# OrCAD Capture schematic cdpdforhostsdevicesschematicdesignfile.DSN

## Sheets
1 2 History_Sheet: title: CD_PD_Hosts_Devices; rev: 1.5
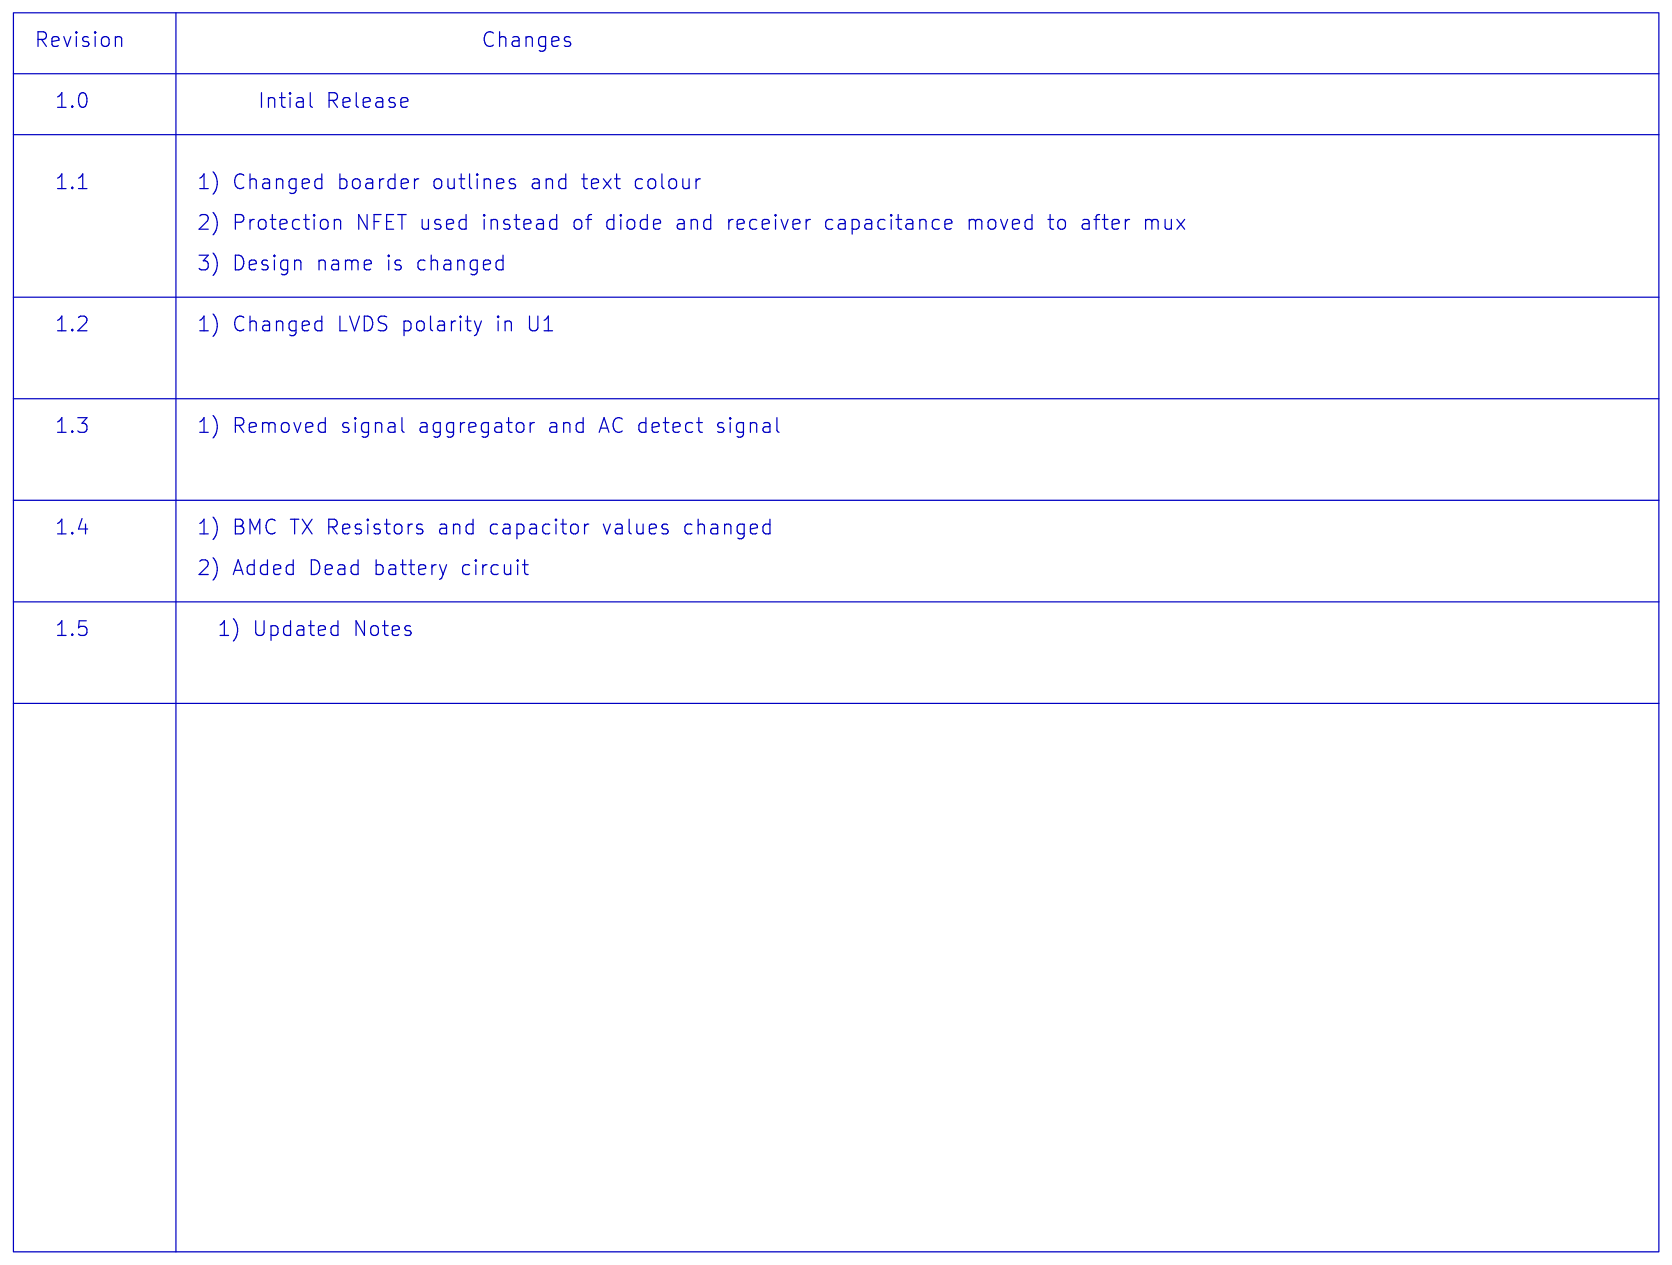
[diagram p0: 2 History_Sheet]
2 1 CD_PD_Host_ Devices: size B
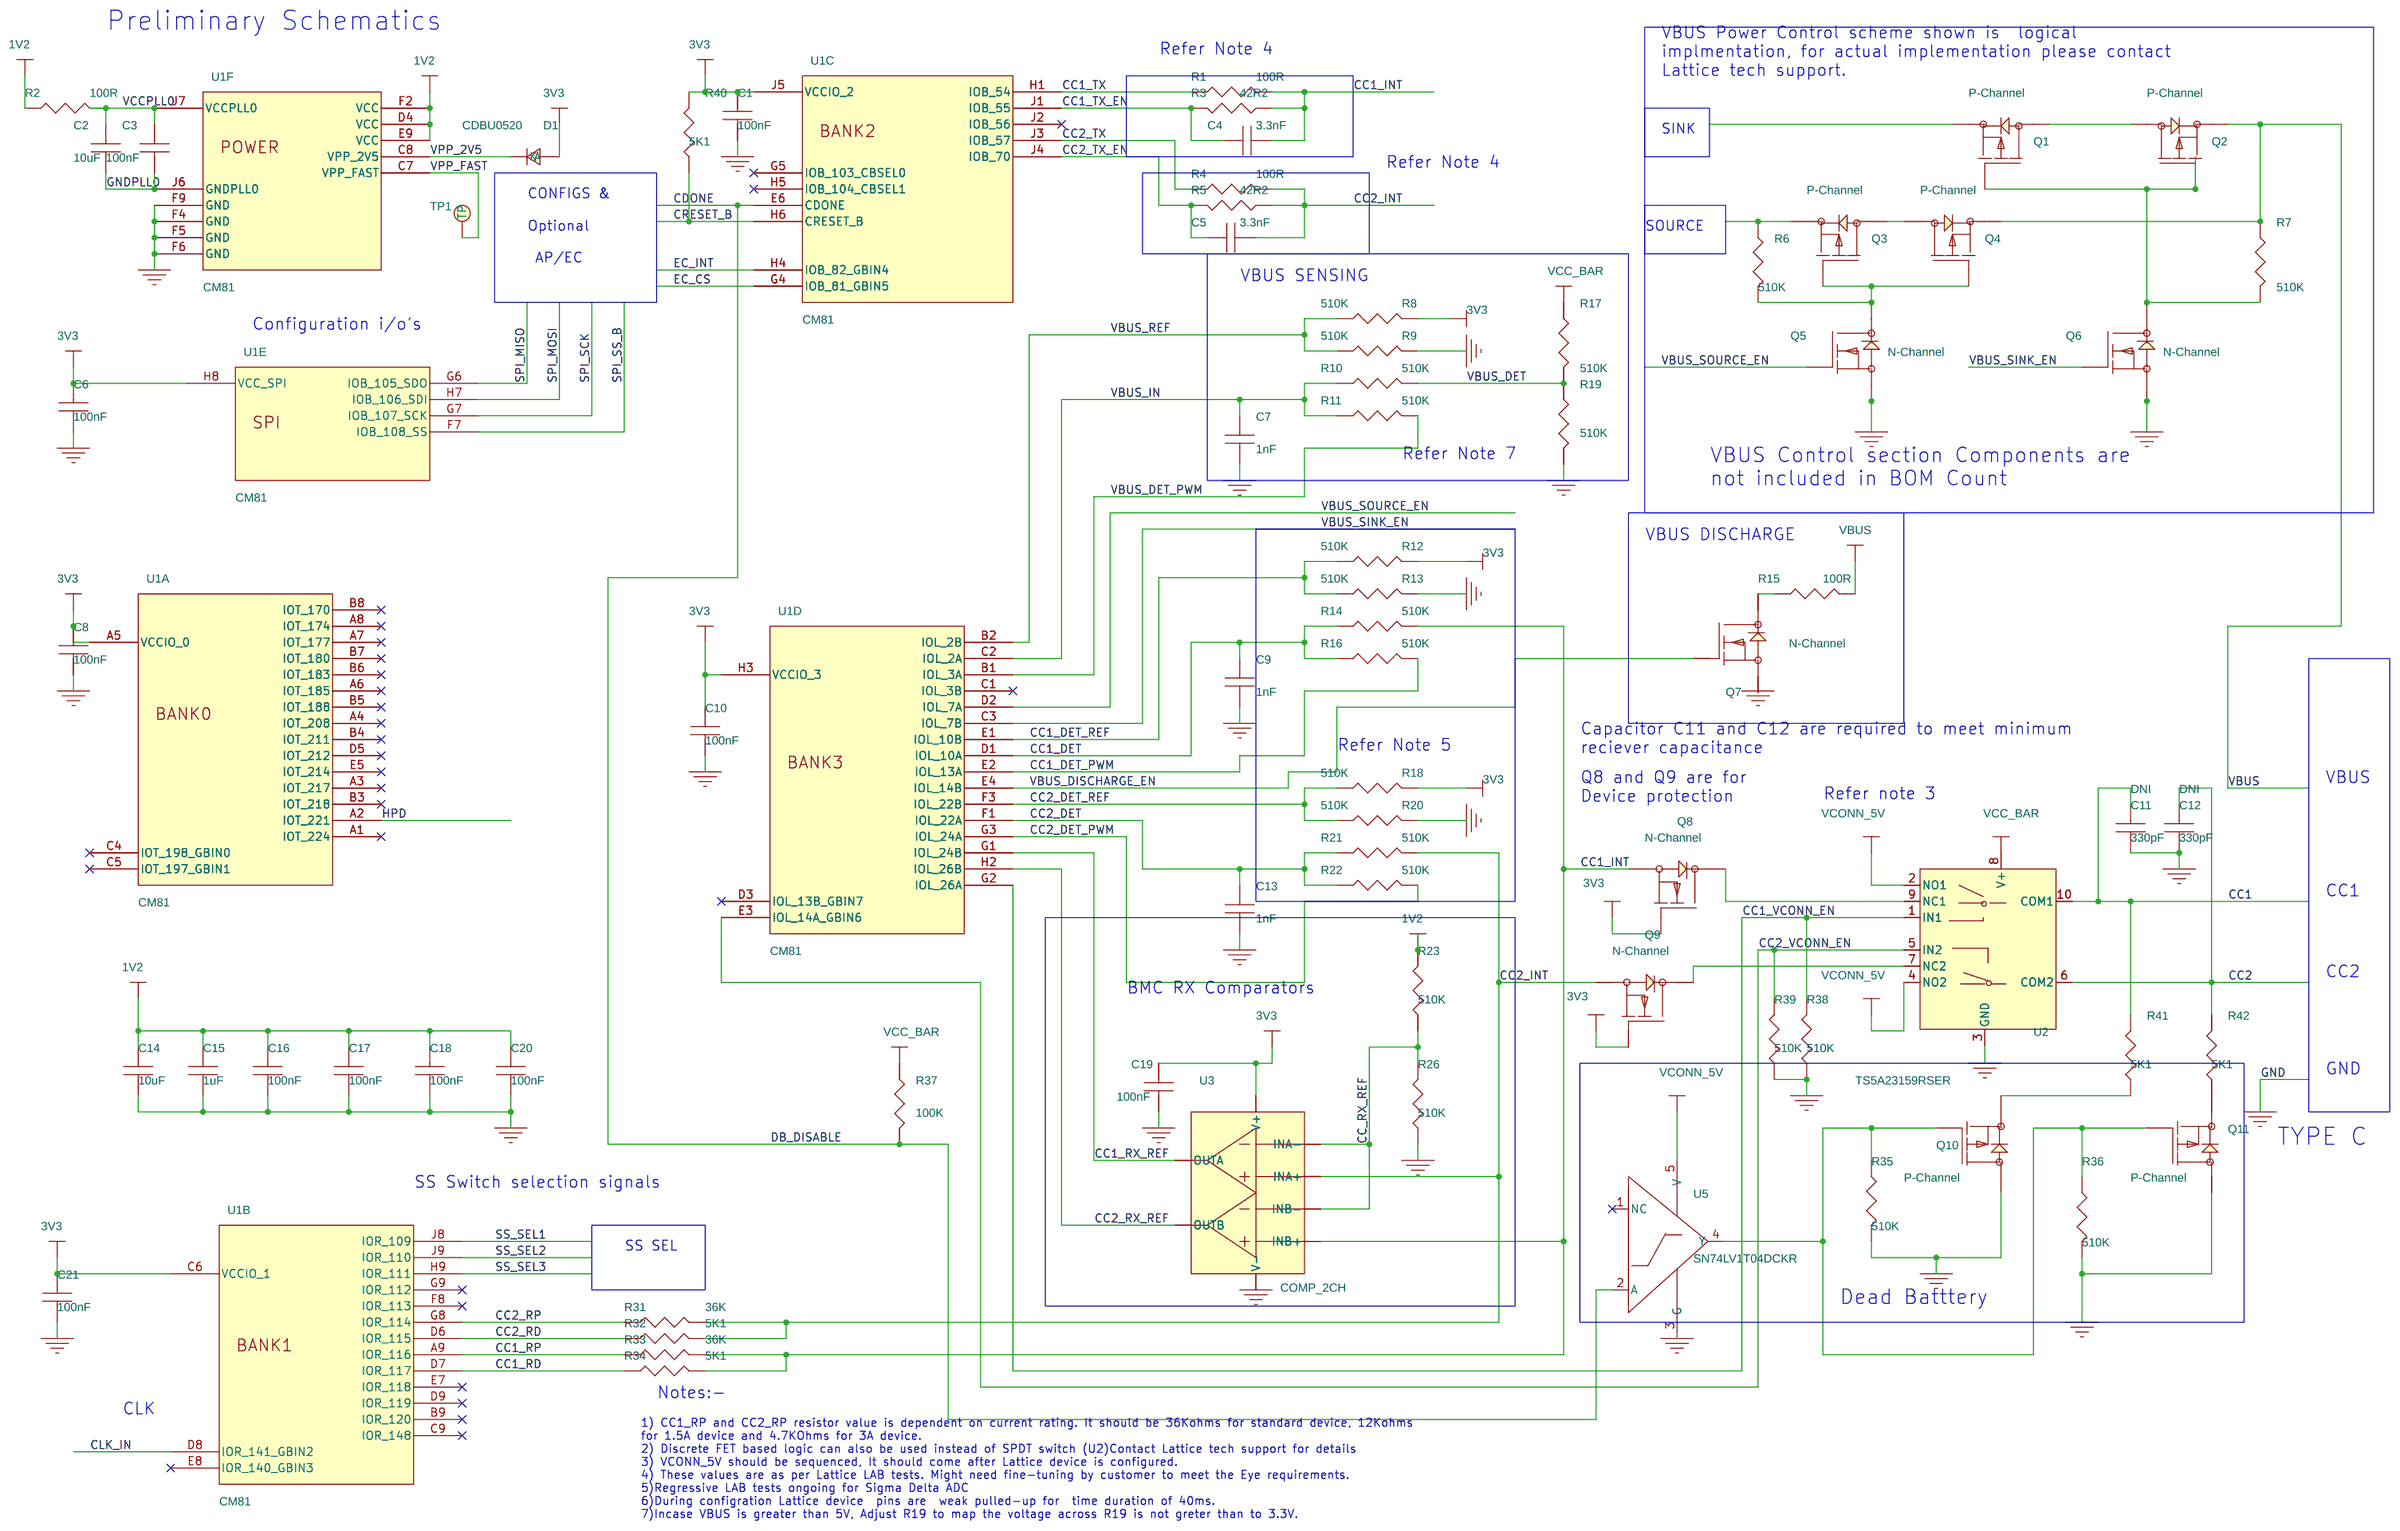
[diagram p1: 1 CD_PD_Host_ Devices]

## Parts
C1  100nF  [C0402]
C2  10uF  [C0805]
C3  100nF  [C0402]
C4  3.3nF  [C0402]
C5  3.3nF  [C0402]
C6  100nF  [C0402]
C7  1nF  [C0402]
C8  100nF  [C0402]
C9  1nF  [C0402]
C10  100nF  [C0402]
C11  330pF  [C0402]
C12  330pF  [C0402]
C13  1nF  [C0402]
C14  10uF  [C0805]
C15  1uF  [C0402]
C16  100nF  [C0402]
C17  100nF  [C0402]
C18  100nF  [C0402]
C19  100nF  [C0402]
C20  100nF  [C0402]
C21  100nF  [C0402]
D1  CDBU0520  [D0603]
Q1  P-Channel
Q2  P-Channel
Q3  P-Channel
Q4  P-Channel
Q5  N-Channel
Q6  N-Channel
Q7  N-Channel
Q8  N-Channel  [BSH103,235]
Q9  N-Channel  [BSH103,235]
Q10  P-Channel  [NTA4151PT1G_SOT416]
Q11  P-Channel  [NTA4151PT1G_SOT416]
R1  100R  [R0402]
R2  100R  [R0402]
R3  42R2  [R0402]
R4  100R  [R0402]
R5  42R2  [R0402]
R6  510K  [R0402]
R7  510K  [R0402]
R8  510K  [R0603]
R9  510K  [R0603]
R10  510K  [R0603]
R11  510K  [R0603]
R12  510K  [R0603]
R13  510K  [R0603]
R14  510K  [R0603]
R15  100R  [R0402]
R16  510K  [R0603]
R17  510K  [R0402]
R18  510K  [R0603]
R19  510K  [R0402]
R20  510K  [R0603]
R21  510K  [R0603]
R22  510K  [R0603]
R23  510K  [R0603]
R26  510K  [R0603]
R31  36K  [R0402]
R32  5K1  [R0402]
R33  36K  [R0402]
R34  5K1  [R0402]
R35  510K  [R0402]
R36  510K  [R0402]
R37  100K  [R0402]
R38  510K  [R0603]
R39  510K  [R0603]
R40  5K1  [R0402]
R41  5K1  [R0402]
R42  5K1  [R0402]
TP1  TP_S_40_63  [tp_s_40_63]
U1  CM81  (sections A,B,C,D,E,F)
U2  TS5A23159RSER  [TS5A23159_10UQFN]
U3  COMP_2CH
U5  SN74LV1T04DCKR  [SC-70-5]

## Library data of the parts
C1 C3 C6 C8 C10 C16-C21 = CAP_CER_100nF_0402_10V
C2 C14 = CAP_CER_10uF_0805_10V
C4 C5 = CAP_CER_3.3nF_0402_10V
C7 C9 C13 = CAP_CER_1nF_0402_10V
C11 C12 = CAP_CER_330pF_0402_16V: BOM_Note: DNI
C15 = CAP_CER_1uF_0402_10V
D1 = DIODE_SCHOTTKY_20V_0603
Q1-Q4 = MOSFET_P-CHAN-1V_6A
Q5 Q6 = MOSFET_N-CHAN-0P45V_0P85A
Q7 = PWR_MOSFET-N-CH-0P9V_6P1A
Q8 Q9 = MOSFET_N-CHAN-0P45V_1
Q10 Q11 = MOSFET_P-CHAN-0P45_0P76A
R1 R4 = RES_100R_1W16_0402_1P
R2 = RES_100R_1W16_0402_5P
R3 R5 = RES_42R_1W16_0402_1P
R6-R14 R16-R23 R26 R35 R36 R38 R39 = RES_500K_1W16_0402_5P
R15 = RES_100R_1W_2512_1P
R31 R33 = RES_36K_1W16_0402_5P
R32 R34 R40-R42 = RES_5K1_1W16_0402_5P
R37 = RES_100K_1W16_0402_5P
TP1 = TP_S_40_63: Assy: DNI
U1 = iCE40LP8K-CM81_0
U2 = SPDT_DUAL
U3 = DUAL_CHANN_COMP
U5 = VLT_BUFF_SC70_NEW

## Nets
1V2: C14.1 C15.1 C16.1 C17.1 C18.1 C20.1 R2.1 R23.2 U1.D4(VCC) U1.E9(VCC) U1.F2(VCC)
3V3: C1.1 C6.1 C8.1 C10.1 C19.1 C21.1 D1.1(A) Q8.1(G) Q9.1(G) R8.1 R12.1 R18.1 R37.1 R40.2 U1.A5(VCCIO_0) U1.C6(VCCIO_1) U1.H3(VCCIO_3) U1.H8(VCC_SPI) U1.J5(VCCIO_2) U3.V+
GND: C1.2 C6.2 C7.2 C8.2 C9.2 C10.2 C11.2 C12.2 C13.2 C14.2 C15.2 C16.2 C17.2 C18.2 C19.2 C20.2 C21.2 Q5.2(S) Q6.2(S) Q7.2(S) Q10.3(D) Q11.3(D) R9.1 R13.1 R19.2 R20.1 R26.1 R35.2 R36.2 R38.1 R39.1 U1.F4(GND) U1.F5(GND) U1.F6(GND) U1.F9(GND) U2.3(GND) U3.V- U5.3(G)
GNDPLL0: C2.2 C3.2 U1.J6(GNDPLL0)
VBUS: Q2.2(S) Q4.2(S) R7.1 R15.2 R17.1
VBUS_DET: R10.2 R17.2 R19.1
VBUS_DET_PWM: R11.2 U1.B1(IOL_3A)
VBUS_DISCHARGE_EN: Q7.1(G) U1.E4(IOL_14B)
VBUS_IN: C7.1 R10.1 R11.1 U1.C2(IOL_2A)
VBUS_REF: R8.2 R9.2 U1.B2(IOL_2B)
VBUS_SINK_EN: Q6.1(G) U1.C3(IOL_7B)
VBUS_SOURCE_EN: Q5.1(G) U1.D2(IOL_7A)
VCCPLL0: C2.1 C3.1 R2.2 U1.J7(VCCPLL0)
CC1: C11.1 R41.2 U2.10(COM1)
CC1_DET: C9.1 R14.1 R16.1 U1.D1(IOL_10A)
CC1_DET_PWM: R16.2 U1.E2(IOL_13A)
CC1_DET_REF: R12.2 R13.2 U1.E1(IOL_10B)
CC1_INT: C4.2 Q8.2(S) R1.2 R3.1 R14.2 R33.2 R34.2 U3.INB+
CC1_RD: R34.1 U1.D7(IOR_117)
CC1_RP: R33.1 U1.A9(IOR_116)
CC1_RX_REF: U1.G1(IOL_24B) U3.OUTA
CC1_TX: R1.1 U1.H1(IOB_54)
CC1_TX_EN: C4.1 R3.2 U1.J1(IOB_55)
CC1_VCONN_EN: R38.2 U1.G2(IOL_26A) U2.1(IN1)
CC2: C12.1 R42.2 U2.6(COM2)
CC2_DET: C13.1 R21.1 R22.1 U1.F1(IOL_22A)
CC2_DET_PWM: R22.2 U1.G3(IOL_24A)
CC2_DET_REF: R18.2 R20.2 U1.F3(IOL_22B)
CC2_INT: C5.2 Q9.2(S) R4.2 R5.1 R21.2 R31.2 R32.2 U3.INA+
CC2_RD: R32.1 U1.D6(IOR_115)
CC2_RP: R31.1 U1.G8(IOR_114)
CC2_RX_REF: U1.H2(IOL_26B) U3.OUTB
CC2_TX: R4.1 U1.J3(IOB_57)
CC2_TX_EN: C5.1 R5.2 U1.J4(IOB_70)
CC2_VCONN_EN: R39.2 U1.E3(IOL_14A_GBIN6) U2.5(IN2)
CC_RX_REF: R23.1 R26.2 U3.INA- U3.INB-
CDONE: R37.2 U1.E6(CDONE) U5.2(A)
CLK_IN: U1.D8(IOR_141_GBIN2)
CRESET_B: R40.1 U1.H6(CRESET_B)
EC_CS: U1.G4(IOB_81_GBIN5)
EC_INT: U1.H4(IOB_82_GBIN4)
HPD: U1.A2(IOT_221)
SPI_MISO: U1.G6(IOB_105_SDO)
SPI_MOSI: U1.H7(IOB_106_SDI)
SPI_SCK: U1.G7(IOB_107_SCK)
SPI_SS_B: U1.F7(IOB_108_SS)
SS_SEL1: U1.J8(IOR_109)
SS_SEL2: U1.J9(IOR_110)
SS_SEL3: U1.H9(IOR_111)
VCONN_5V: U2.2(NO1) U2.4(NO2) U2.8(V+) U5.5(V)
VPP_2V5: D1.2(K) U1.C8(VPP_2V5)
VPP_FAST: TP1.1(TP) U1.C7(VPP_FAST)
N60696: Q1.1(G) Q2.1(G) Q6.3(D) R7.2
N64442: Q1.3(D) Q2.3(D)
N64482: Q3.1(G) Q4.1(G) Q5.3(D) R6.2
N64582: Q3.2(S) R6.1
N67034: Q3.3(D) Q4.3(D)
N71063: Q7.3(D) R15.1
N75649: Q8.3(D) U2.9(NC1)
N75875: Q9.3(D) U2.7(NC2)
N88003: Q10.1(G) Q11.1(G) R35.1 R36.1 U5.4(Y)
N88261: Q10.2(S) R41.1
N112730: Q11.2(S) R42.1

Not connected (* = marked no-connect by the designer): Q1 2(S); U1 A1(IOT_224)* A3(IOT_217)* A4(IOT_208)* A6(IOT_185)* A7(IOT_177)* A8(IOT_174)* B3(IOT_218)* B4(IOT_211)* B5(IOT_188)* B6(IOT_183)* B7(IOT_180)* B8(IOT_170)* B9(IOR_120)* C1(IOL_3B)* C4(IOT_198_GBIN0)* C5(IOT_197_GBIN1)* C9(IOR_148)* D3(IOL_13B_GBIN7)* D5(IOT_212)* D9(IOR_119)* E5(IOT_214)* E7(IOR_118)* E8(IOR_140_GBIN3)* F8(IOR_113)* G5(IOB_103_CBSEL0)* G9(IOR_112)* H5(IOB_104_CBSEL1)* J2(IOB_56)*; U5 1(NC)*

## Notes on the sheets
sheet 1
- Revision
- Changes
- 1.0
- Intial Release
- 1.1
- 1) Changed boarder outlines and text colour
- 2) Protection NFET used instead of diode and receiver capacitance moved to after mux
- 3) Design name is changed
- 1.2
- 1) Changed LVDS polarity in U1
- 1.3
- 1) Removed signal aggregator and AC detect signal
- 1.4
- 1) BMC TX Resistors and capacitor values changed
- 2) Added Dead battery circuit
- 1.5
- 1) Updated Notes
sheet 2
- Preliminary Schematics
- VBUS Power Control scheme shown is  logical
  implmentation, for actual implementation please contact
  Lattice tech support.
- Refer Note 4
- SINK
- Refer Note 4
- CONFIGS &
- Optional
   AP/EC
- SOURCE
- VBUS SENSING
- Configuration i/o's
- Refer Note 7
- VBUS Control section Components are
  not included in BOM Count
- VBUS DISCHARGE
- Capacitor C11 and C12 are required to meet minimum
  reciever capacitance
- Refer Note 5
- Q8 and Q9 are for
  Device protection
- VBUS
- Refer note 3
- CC1
- CC2
- BMC RX Comparators
- GND
- TYPE C
- SS Switch selection signals
- SS SEL
- Dead Batttery
- Notes:-
- CLK
- 1) CC1_RP and CC2_RP resistor value is dependent on current rating. It should be 36Kohms for standard device, 12Kohms
  for 1.5A device and 4.7KOhms for 3A device.
  2) Discrete FET based logic can also be used instead of SPDT switch (U2)Contact Lattice tech support for details
  3) VCONN_5V should be sequenced, It should come after Lattice device is configured.
  4) These values are as per Lattice LAB tests. Might need fine-tuning by customer to meet the Eye requirements.
  5)Regressive LAB tests ongoing for Sigma Delta ADC
  6)During configration Lattice device  pins are  weak pulled-up for  time duration of 40ms.
  7)Incase VBUS is greater than 5V, Adjust R19 to map the voltage across R19 is not greter than to 3.3V.
